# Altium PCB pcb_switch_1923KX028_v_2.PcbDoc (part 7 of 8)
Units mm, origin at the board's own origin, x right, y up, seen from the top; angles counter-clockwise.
Board outline 297.2 x 112.05 mm, 6 copper layers (Component Side, GND Layer 1, Inner Layer 1, Inner Layer 2, GND Layer 2, Solder Side), stack 1.578 mm thick; 545 components, 377 nets, 3174 pads, 1537 vias.
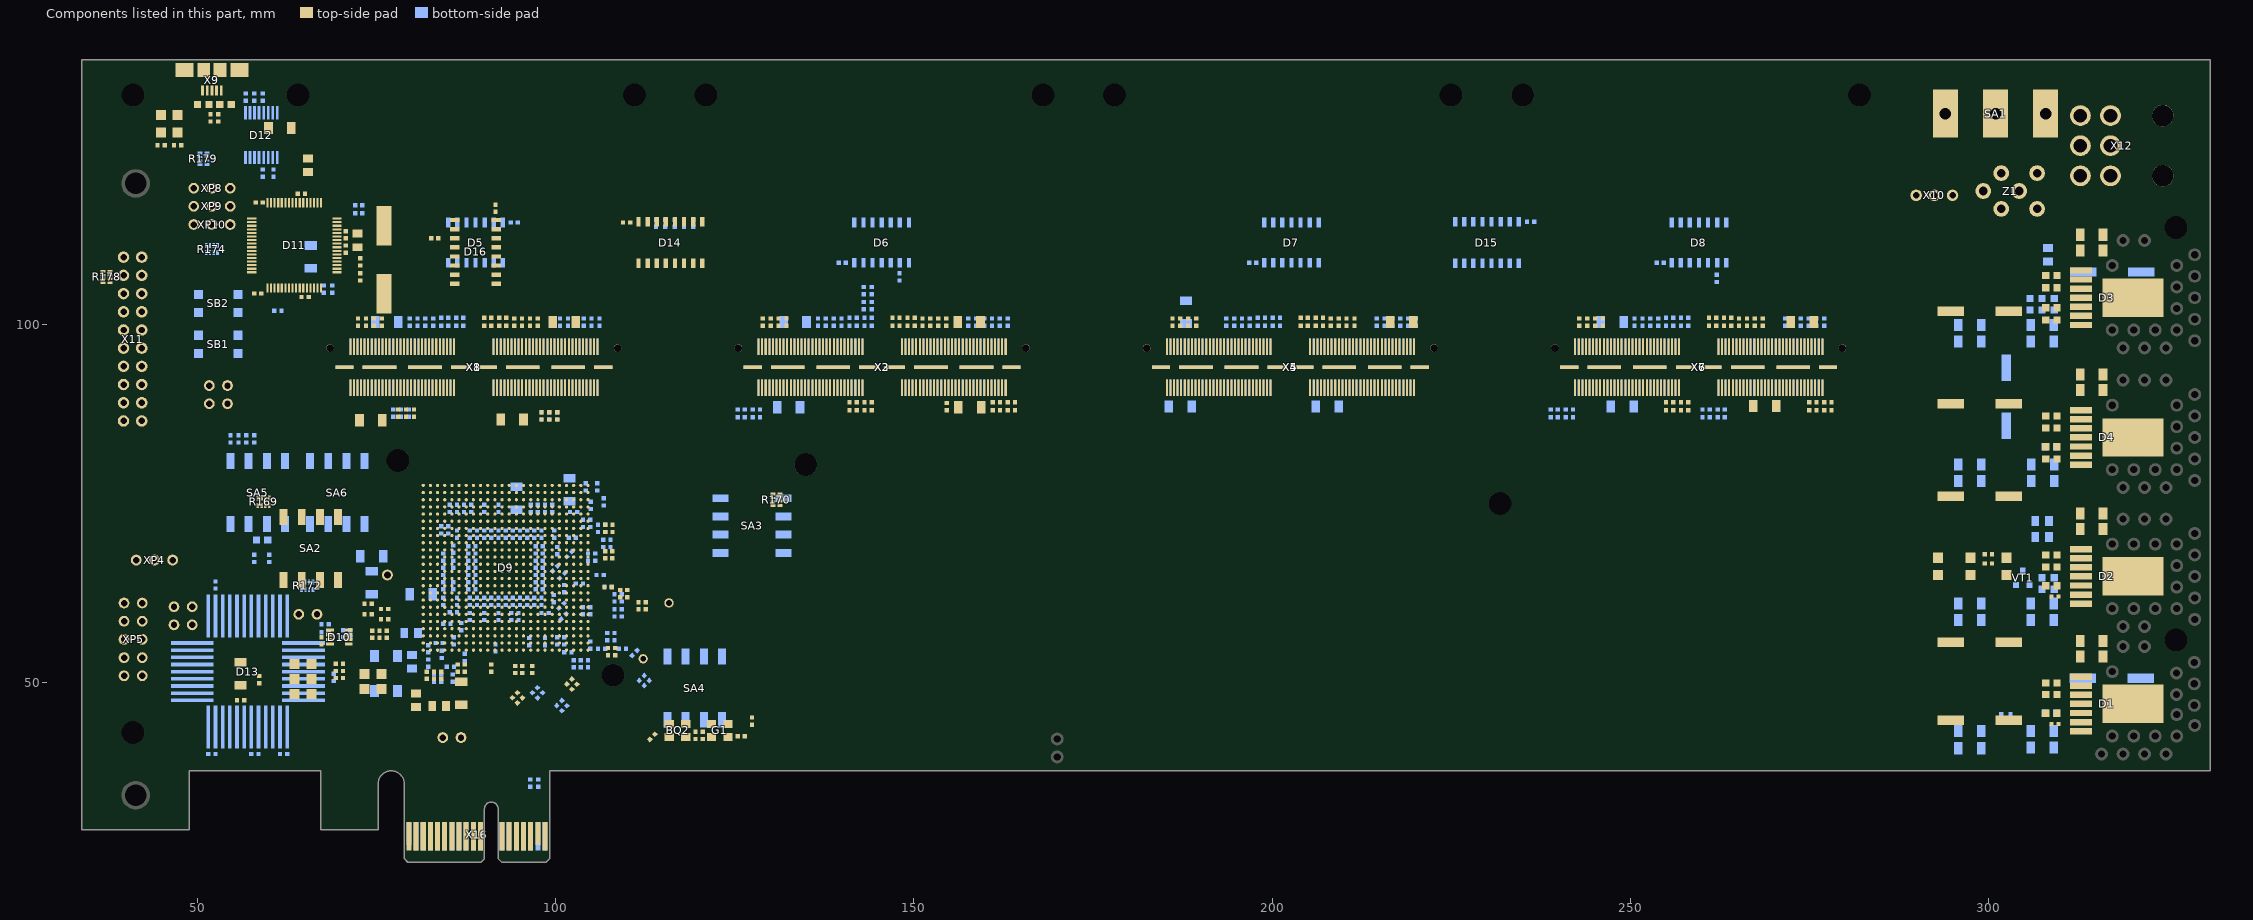
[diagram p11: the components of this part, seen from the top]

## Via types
v1: diameter 0.8, hole 0.4, Component Side to Solder Side, tented both sides, 884 vias
v2: diameter 0.5, hole 0.3, Component Side to Solder Side, tented both sides, 269 vias
v3: diameter 1, hole 0.6, Component Side to Solder Side, tented both sides, 95 vias
v4: diameter 0.5/0.5/0.3/0.3/0.5/0.5 (per signal layer), hole 0.3, Component Side to Solder Side, tented both sides, 80 vias
v5: diameter 0.5/0.3/0.3/0.5/0.3/0.5 (per signal layer), hole 0.3, Component Side to Solder Side, tented both sides, 37 vias
v6: diameter 0.5/0.3/0.3/0.3/0.3/0.5 (per signal layer), hole 0.3, Component Side to Solder Side, tented both sides, 34 vias
v7: diameter 0.5/0.5/0.5/0.3/0.5/0.5 (per signal layer), hole 0.3, Component Side to Solder Side, tented both sides, 29 vias
v8: diameter 0.5, hole 0.3, Component Side to Solder Side, 25 vias
v9: diameter 0.5/0.3/0.5/0.3/0.3/0.5 (per signal layer), hole 0.3, Component Side to Solder Side, tented both sides, 25 vias
v10: diameter 0.5/0.5/0.3/0.5/0.5/0.5 (per signal layer), hole 0.3, Component Side to Solder Side, tented both sides, 19 vias
v11: diameter 0.6, hole 0.3, Component Side to Solder Side, tented both sides, 14 vias
v12: diameter 0.8, hole 0.5, Component Side to Solder Side, tented both sides, 11 vias
v13: diameter 0.5/0.3/0.5/0.5/0.3/0.5 (per signal layer), hole 0.3, Component Side to Solder Side, tented both sides, 7 vias
v14: diameter 0.8, hole 0.4, Component Side to Solder Side, 5 vias
v15: diameter 0.5/0.5/0.5/0.5/0.5/0.5 (per signal layer), hole 0.3, Component Side to Solder Side, tented both sides, 2 vias
v16: diameter 0.8, hole 0.5, Component Side to Solder Side, 1 vias

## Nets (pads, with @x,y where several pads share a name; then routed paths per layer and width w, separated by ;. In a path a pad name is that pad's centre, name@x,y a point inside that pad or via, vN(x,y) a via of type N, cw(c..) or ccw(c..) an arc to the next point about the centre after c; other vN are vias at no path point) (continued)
pads on no net: BQ2.2 BQ2.4 D9.A4 D9.A5 D9.A6 D9.A10 D9.A11 D9.A12 D9.A13 D9.A18 D9.A19 D9.A20 D9.AA8 D9.AA9 D9.AA19 D9.AB19 D9.AC13 D9.AD13 D9.AD23 D9.B5 D9.B6 D9.B7 D9.B10 D9.B11 D9.B12 D9.B13 D9.B18 D9.B19 D9.C5 D9.C6 D9.C12 D9.C17 D9.C18 D9.C19 D9.D5 D9.D6 D9.D7 D9.D11 D9.D12 D9.D17 D9.D18 D9.D19 D9.G1 D9.H2 D9.H23 D9.J1 D9.J2 D9.J4 D9.K1 D9.K2 D9.K3 D9.K4 D9.K23 D9.K24 D9.L2 D9.L4 D9.R2 D9.R4 D9.T1 D9.T2 D9.T3 D9.T4 D9.U1 D9.U2 D9.U3 D9.U21 D9.U22 D9.V1 D9.V4 D11.9 D11.10 D11.14 D11.16 D11.29 D11.34 D11.37 D11.50 D12.15 D12.16 D13.14 D13.18 D13.19 D13.22 D13.23 D13.24 D13.25 D13.28 D15.9 R174.4 R174.8 SA1.3 SB1.2 SB1.4 SB2.2 SB2.4 X1.0 X1.2 X1.3 X1.4 X1.7 X1.9 X1.11 X1.13 X1.15 X1.16 X1.17 X1.18 X1.19 X1.20 X1.21 X1.22 X1.25 X1.26 X1.30 X1.32 X1.37 X1.63 X1.67 X1.69 X1.71 X1.73 X1.75 X1.76 X1.77 X1.78 X1.79 X1.80 X1.81 X1.82 X1.85 X1.86 X1.90 X1.92 X1.97 X2.0 X2.2 X2.3 X2.4 X2.7 X2.9 X2.11 X2.13 X2.15 X2.16 X2.17 X2.18 X2.19 X2.20 X2.21 X2.22 X2.25 X2.26 X2.29 X2.30 X2.31 X2.32 X2.35 X2.37 X2.63 X2.67 X2.69 X2.71 X2.73 X2.75 X2.76 X2.77 X2.78 X2.79 X2.80 X2.81 X2.82 X2.85 X2.86 X2.89 X2.90 X2.91 X2.92 X2.95 X2.97 X3.0 X3.3 X3.7 X3.9 X3.11 X3.13 X3.15 X3.16 X3.17 X3.18 X3.19 X3.20 X3.21 X3.22 X3.25 X3.26 X3.29 X3.30 X3.31 X3.32 X3.35 X3.37 X3.63 X3.67 X3.69 X3.71 X3.73 X3.75 X3.76 X3.77 X3.78 X3.79 X3.80 X3.81 X3.82 X3.85 X3.86 X3.89 X3.90 X3.91 X3.92 X3.95 X3.97 X4.0 X4.2 X4.3 X4.4 X4.7 X4.9 X4.11 X4.13 X4.15 X4.16 X4.17 X4.18 X4.19 X4.20 X4.21 X4.22 X4.25 X4.26 X4.29 X4.30 X4.31 X4.32 X4.35 X4.37 X4.63 X4.67 X4.69 X4.71 X4.73 X4.75 X4.76 X4.77 X4.78 X4.79 X4.80 X4.81 X4.82 X4.85 X4.86 X4.89 X4.90 X4.91 X4.92 X4.95 X4.97 X5.0 X5.3 X5.7 X5.9 X5.11 X5.13 X5.15 X5.16 X5.17 X5.18 X5.19 X5.20 X5.21 X5.22 X5.25 X5.26 X5.29 X5.30 X5.31 X5.32 X5.35 X5.37 X5.63 X5.67 X5.69 X5.71 X5.73 X5.75 X5.76 X5.77 X5.78 X5.79 X5.80 X5.81 X5.82 X5.85 X5.86 X5.89 X5.90 X5.91 X5.92 X5.95 X5.97 X6.0 X6.2 X6.3 X6.4 X6.7 X6.9 X6.11 X6.13 X6.15 X6.16 X6.17 X6.18 X6.19 X6.20 X6.21 X6.22 X6.25 X6.26 X6.29 X6.30 X6.31 X6.32 X6.35 X6.37 X6.63 X6.67 X6.69 X6.71 X6.73 X6.75 X6.76 X6.77 X6.78 X6.79 X6.80 X6.81 X6.82 X6.85 X6.86 X6.89 X6.90 X6.91 X6.92 X6.95 X6.97 X7.0 X7.3 X7.7 X7.9 X7.11 X7.13 X7.15 X7.16 X7.17 X7.18 X7.19 X7.20 X7.21 X7.22 X7.25 X7.26 X7.29 X7.30 X7.31 X7.32 X7.35 X7.37 X7.63 X7.67 X7.69 X7.71 X7.73 X7.75 X7.76 X7.77 X7.78 X7.79 X7.80 X7.81 X7.82 X7.85 X7.86 X7.89 X7.90 X7.91 X7.92 X7.95 X7.97 X8.0 X8.3 X8.7 X8.9 X8.11 X8.13 X8.15 X8.16 X8.17 X8.18 X8.19 X8.20 X8.21 X8.22 X8.25 X8.26 X8.30 X8.32 X8.37 X8.63 X8.67 X8.69 X8.71 X8.73 X8.75 X8.76 X8.77 X8.78 X8.79 X8.80 X8.81 X8.82 X8.85 X8.86 X8.90 X8.92 X8.97 X9.1 X9.4 X10.2 X12.7 X12.8 X16.A2 X16.A3 X16.A5 X16.A6 X16.A7 X16.A8 X16.A9 X16.A10 X16.B1 X16.B2 X16.B3 X16.B5 X16.B6 X16.B8 X16.B9 X16.B10 X16.B11 X16.B12

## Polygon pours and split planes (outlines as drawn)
D9_1.1V on Inner Layer 1 "TL_D9_1.1V" (solid, remove dead copper, pour order 866): 31 vertices, not listed, extent 83.4,46.7 105.705,71.7
NET_FIL_3.3V on Inner Layer 1 "IL1_NET_FIL_3.3" (solid, remove dead copper, pour order 865): 33 vertices, not listed, extent 85.8,43.3 111.9,71.4
NET_FIL_3.3V on Inner Layer 1 "IL1_NET_FIL_3.3" (solid, remove dead copper, pour order 859): 29 vertices, not listed, extent 81.7,43.3 91.4,57.9
+3.3V on Inner Layer 1 "ALL_+3.3" (solid, remove dead copper, pour order 867): 46 vertices, not listed, extent 36,38.5 307.2,127
D9_1.1V_PCIE on Inner Layer 1 "TL_D9_1.1V_PCIE" (solid, pour order 860): 84.2,52.6 85.8,52.6 86.3,53.1 86.3,57.4 86.2,57.5 85,57.5 83.8,56.3 83.8,53
+12 on Inner Layer 1 "IL2_12V" (solid, pour order 864): 316.2,119 315.2,120 315.2,132.5 314.7,133 310.2,133 309.7,132.5 309.7,126.1 306.3,126.1 306.3,135.1 307.7,136.5 316.2,136.5 318.9,133.8 318.9,119.7 318.2,119
NetSA1_2 on Inner Layer 1 "IL2_NetSA1_2" (solid, pour order 863): 18 vertices, not listed, extent 299.1,119.5 303.4,132.7
NetX12_4 on Inner Layer 1 "TL_NetXP3_4" (solid, pour order 862): 305.2,125 305.2,120.2 305.9,119.5 309.2,119.5 309.7,119 313.7,119 314.7,120 314.7,132.2 314.4,132.5 310.7,132.5 310.2,132 310.2,126 309.8,125.6 305.8,125.6
INPUTPWR on Inner Layer 1 "Inner_Layer_1_INPUTPWR" (solid, pour order 861): 301,117.8 303.2,117.8 306.2,114.8 310.3,114.8 312.9,112.2 312.9,108.7 312.2,108 305.7,108 300.2,113.5 300.2,117
GND on Inner Layer 1 "TL_DIRTY_GND" (solid, pour order 868): 316.7,136.9 316.7,120.8 309.5,120.8 305.2,116.5 305.2,114.7 305.4,114.5 310.9,114.5 313.4,112 313.4,74.5 313.4,66.4 313.4,55.5 313.4,37.7 330.9,37.7 331,37.8 331,136.9
GND on Inner Layer 1 "IL1_GND" (solid, remove dead copper, pour order 869): 34 vertices, not listed, extent 34.1,25.2 312.9,136.65
+3.3V on Component Side "TL_3.3" (solid, remove dead copper, pour order 852): 158.1,89.9 161.5,89.9 161.5,88.5 160.2,88.5 160.2,87.2 160,87 158.3,87 158.1,87.2
+3.3V on Component Side "ALL_+3.3" (solid, pour order 810): 29 vertices, not listed, extent 298.5,73.7 314.5,103.7
D9_1.1V on Component Side "TL_D9_1.1V" (solid, pour order 813): 80.4,49 81.7,49 82.5,49.8 84.2,49.8 86.1,49.8 86.4,49.5 86.4,47.9 86.1,47.6 81.8,47.6 81.5,47.9 80.4,47.9
NET_FIL_3.3V on Component Side "TL_NET_FIL_3.3V" (solid, pour order 811): 84.1,46.8 84.1,46 83.9,45.8 83.9,45 84.2,44.7 85.8,44.7 86,44.9 86,45.5 85.8,45.7 85.5,45.7 85.2,46 85.2,46.8
+3.3V on Component Side "TL_3.3V" (solid, pour order 814): 83.4,43.6 83.7,43.9 83.7,45.6 83.3,46 83.3,46.8 82.2,46.8 82.2,46 81.9,45.7 80.8,45.7 80.5,45.4 80.5,43.9 80.8,43.6
+1.1V on Component Side "TL_1.1V" (solid, pour order 815): 75.5,47.8 75.2,47.5 75.2,45.9 75.5,45.6 79.4,45.6 79.8,46 80.5,46 80.5,47.1 79.8,47.1 79.1,47.8
GND on Component Side "CS_GND_DIRECT_CONN" (solid, pour order 854): 297.7,121 297.7,114.011 297.711,114 313.2,114 313.2,121
INPUTPWR on Component Side "Inner_Layer_1_INPUTPWR" (solid, pour order 816): 17 vertices, not listed, extent 309.4,50.4 314.4,56.5
INPUTPWR on Component Side "Inner_Layer_1_INPUTPWR" (solid, pour order 818): 309.8,74.3 309.4,73.9 309.4,69.5 309.7,69.2 311.3,69.2 311.4,69.1 311.4,68.2 314.4,68.2 314.4,69 313.3,70.1 313.3,72 312,72 312,73 313.3,73 313.3,74.3
INPUTPWR on Component Side "Inner_Layer_1_INPUTPWR" (solid, pour order 819): 18 vertices, not listed, extent 309.4,87.6 314.4,93.7
+12 on Component Side "IL2_12V" (solid, pour order 807): 316.2,119 315.2,120 315.2,132.5 314.7,133 310.2,133 309.7,132.5 309.7,126.1 306.3,126.1 306.3,135.1 307.8,136.6 316.1,136.6 318.9,133.8 318.9,119.7 318.2,119
NetX12_4 on Component Side "TL_NetXP3_4" (solid, pour order 808): 313.7,119 314.7,120 314.7,132.2 314.4,132.5 310.7,132.5 310.2,132 310.2,126 309.8,125.6 308.8,125.6 305.8,125.6 305.2,125 305.2,120.2 305.9,119.5 309.2,119.5 309.7,119
NetSA1_2 on Component Side "IL2_NetSA1_2" (solid, pour order 809): 18 vertices, not listed, extent 299.1,119.5 303.4,132.7
INPUTPWR on Component Side "Inner_Layer_1_INPUTPWR" (solid, pour order 817): 19 vertices, not listed, extent 309.2,107.1 314.4,113.2
GND on Component Side "TL_DIRTY_GND" (solid, pour order 855): 26 vertices, not listed, extent 312.2,38.1 331,136.9
USB_3.3V on Component Side "TL_USB_3.3V" (solid, pour order 812): 57.1,128.1 57.4,128.4 59.1,128.4 59.3,128.2 60,128.2 60,126.6 59.3,126.6 59.1,126.4 57.4,126.4 57.1,126.7
+1.1V on Component Side "ALL_+1.1" (solid, pour order 820): 25 vertices, not listed, extent 298.5,38.1 314.5,62
+1.1V on Component Side "TL_1.1" (solid, remove dead copper, pour order 821): 79.5,102.5 79,102 79,100.2 80.8,98.4 84.6,98.4 84.6,102 84.1,102.5
+3.3V on Component Side "TL_3.3" (solid, remove dead copper, pour order 822): 80.8,93.3 81,93.5 84.6,93.5 84.8,93.3 84.8,92.7 84.6,92.5 81,92.5 80.8,92.7
+1.1V on Component Side "TL_1.1" (solid, remove dead copper, pour order 824): 100.9,95.3 101.1,95.5 104.7,95.5 104.9,95.3 104.9,94.7 104.7,94.5 101.1,94.5 100.9,94.7
+3.3V on Component Side "TL_3.3" (solid, remove dead copper, pour order 823): 101.1,93.3 101.3,93.5 104.3,93.5 104.5,93.3 104.5,92.5 101.3,92.5 101.1,92.7
+1.1V on Component Side "TL_1.1" (solid, remove dead copper, pour order 826): 92.3,95.3 92.5,95.5 96.1,95.5 96.3,95.3 96.3,94.7 96.1,94.5 92.5,94.5 92.3,94.7
+3.3V on Component Side "TL_3.3" (solid, remove dead copper, pour order 825): 92.3,93.3 92.5,93.5 96.1,93.5 96.3,93.3 96.3,92.7 96.1,92.5 92.5,92.5 92.3,92.7
+1.1V on Component Side "TL_1.1" (solid, remove dead copper, pour order 827): 101.2,98.3 104.5,98.3 104.5,99.1 104.1,99.5 103.6,99.5 103.4,99.7 103.4,100.5 102.2,100.5 102.2,99.7 102,99.5 101.6,99.5 101.2,99.1
+3.3V on Component Side "TL_3.3" (solid, remove dead copper, pour order 828): 20 vertices, not listed, extent 92.2,84.4 104.5,89.7
+1.1V on Component Side "TL_1.1" (solid, remove dead copper, pour order 829): 129.4,95.2 129.6,95.4 133.2,95.4 133.4,95.2 133.4,94.6 133.2,94.4 129.6,94.4 129.4,94.6
+1.1V on Component Side "TL_1.1" (solid, remove dead copper, pour order 830): 137.8,95.2 138,95.4 141.6,95.4 141.8,95.2 141.8,94.6 141.6,94.4 138,94.4 137.8,94.6
+1.1V on Component Side "TL_1.1" (solid, remove dead copper, pour order 831): 149.5,95.2 149.7,95.4 153.3,95.4 153.5,95.2 153.5,94.6 153.3,94.4 149.7,94.4 149.5,94.6
+1.1V on Component Side "TL_1.1" (solid, remove dead copper, pour order 832): 157.6,95.2 157.8,95.4 161.4,95.4 161.6,95.2 161.6,94.6 161.4,94.4 157.8,94.4 157.6,94.6
+3.3V on Component Side "TL_3.3" (solid, remove dead copper, pour order 833): 129.4,93.3 129.6,93.5 133.2,93.5 133.4,93.3 133.4,92.7 133.2,92.5 129.6,92.5 129.4,92.7
+3.3V on Component Side "TL_3.3" (solid, remove dead copper, pour order 835): 137.8,93.3 138,93.5 141.6,93.5 141.8,93.3 141.8,92.7 141.6,92.5 138,92.5 137.8,92.7
+3.3V on Component Side "TL_3.3" (solid, remove dead copper, pour order 834): 149.4,93.3 149.6,93.5 153.2,93.5 153.4,93.3 153.4,92.7 153.2,92.5 149.6,92.5 149.4,92.7
+3.3V on Component Side "TL_3.3" (solid, remove dead copper, pour order 836): 157.8,93.3 158,93.5 161.6,93.5 161.8,93.3 161.8,92.7 161.6,92.5 158,92.5 157.8,92.7
+3.3V on Component Side "TL_3.3" (solid, remove dead copper, pour order 837): 186.3,93.3 186.5,93.5 190.1,93.5 190.3,93.3 190.3,92.7 190.1,92.5 186.5,92.5 186.3,92.7
+3.3V on Component Side "TL_3.3" (solid, remove dead copper, pour order 838): 194.7,93.3 194.9,93.5 198.5,93.5 198.7,93.3 198.7,92.7 198.5,92.5 194.9,92.5 194.7,92.7
+3.3V on Component Side "TL_3.3" (solid, remove dead copper, pour order 839): 207.2,93.4 207.3,93.5 210.9,93.5 211.1,93.3 211.1,92.7 210.9,92.5 207.3,92.5 207.2,92.6
+3.3V on Component Side "TL_3.3" (solid, remove dead copper, pour order 840): 214.1,93.3 214.3,93.5 217.9,93.5 218.1,93.3 218.1,92.7 217.9,92.5 214.3,92.5 214.1,92.7
+1.1V on Component Side "TL_1.1" (solid, remove dead copper, pour order 841): 70.8,102.2 71,102.4 74.6,102.4 74.8,102.2 74.8,101.6 74.6,101.4 71,101.4 70.8,101.6
+3.3V on Component Side "TL_3.3" (solid, remove dead copper, pour order 842): 72.3,93.3 72.5,93.5 76.1,93.5 76.3,93.3 76.3,92.7 76.1,92.5 72.5,92.5 72.3,92.7
+3.3V on Component Side "TL_3.3" (solid, remove dead copper, pour order 843): 20 vertices, not listed, extent 72.2,84.2 84.8,89.7
+1.1V on Component Side "TL_1.1" (solid, remove dead copper, pour order 844): 158.1,98.3 161,98.3 161,99.1 160.6,99.5 160.1,99.5 159.9,99.7 159.9,100.5 158.7,100.5 158.7,99.7 158.5,99.5 158.3,99.5 158.1,99.3
+1.1V on Component Side "TL_1.1" (solid, remove dead copper, pour order 845): 198.5,98.2 195,98.2 193.9,99.3 190,99.3 189,100.3 189,102.4 189.2,102.6 196.5,102.6 198.5,100.6
+3.3V on Component Side "TL_3.3" (solid, remove dead copper, pour order 846): 213.7,88.6 213.7,87.7 214.1,87.3 216.5,87.3 218.3,89.1 218.5,89.3 218.5,89.7 214.8,89.7
+1.1V on Component Side "TL_1.1" (solid, remove dead copper, pour order 847): 218.5,98.3 214.8,98.3 213.8,99.3 211.2,99.3 210.6,99.9 210.6,102.3 210.9,102.6 216.5,102.6 218.5,100.6
+1.1V on Component Side "TL_1.1" (solid, remove dead copper, pour order 848): 255.5,98.3 251.8,98.3 250.8,99.3 246.7,99.3 246,100 246,102.3 246.3,102.6 252.5,102.6 255.5,99.6
+1.1V on Component Side "TL_1.1" (solid, remove dead copper, pour order 849): 275.5,98.3 271.8,98.3 270.8,99.3 270.4,99.7 268.8,101.3 268.8,102.1 269.1,102.4 274.4,102.4 274.8,102 274.8,99.2 275.5,99.2
+3.3V on Component Side "TL_3.3" (solid, remove dead copper, pour order 850): 255.5,89.7 255.5,88.6 254.4,87.5 251.7,87.5 251.4,87.8 251.4,87.9 251.4,89.4 251.7,89.7
+3.3V on Component Side "TL_3.3" (solid, remove dead copper, pour order 851): 275.5,89.7 275.5,88.6 274.7,87.8 274.7,87.2 274.2,86.7 270.3,86.7 270.1,86.9 270.1,89.5 270.3,89.7
GND on Component Side "TL_GND_X" (solid, pour order 853): 67.1,95 67.1,93.1 282.7,93 282.7,95
GND on Component Side "TL_GND" (solid, remove dead copper, pour order 856): 314.3,38 314.3,136.5 34.3,136.5 34.3,78 105.5,78 105.5,38.1
GND on Component Side "TL_GND" (solid, remove dead copper, pour order 857): 27 vertices, not listed, extent 34.2,29.8 108.197,80
GND on Component Side "TL_GND_1923" (solid, remove dead copper, pour order 858): 78.5,80 108,80 108,51 78.5,51
+3.3V on Solder Side "TL_3.3" (solid, remove dead copper, pour order 935): 77.9,64.5 77.6,64.2 77.6,63.7 77.8,63.5 81.3,63.5 81.6,63.2 81.6,61.5 83.3,61.5 83.3,63.7 82.5,64.5 80.8,64.5
+1.1V on Solder Side "TL_1.1V" (solid, remove dead copper, pour order 931): 77.6,63 77.3,63.3 75.6,63.3 75.2,62.9 74.3,62.9 74.3,61.7 75.2,61.7 75.7,61.2 77.3,61.2 77.6,61.5
+3.3V on Solder Side "BL_3.3" (solid, remove dead copper, pour order 939): 80.8,45.7 80.6,45.5 80.6,43.9 80.8,43.7 83.3,43.7 83.5,43.9 83.5,45.5 83.3,45.7
D9_1.1V on Solder Side "BL_D9_1.1" (solid, remove dead copper, pour order 937): 83.7,49.7 83.5,49.5 83.5,47.9 83.7,47.7 86.2,47.7 86.4,47.9 86.4,49.5 86.2,49.7
+1.1V on Solder Side "BL_1.1" (solid, remove dead copper, pour order 933): 17 vertices, not listed, extent 75.3,45.7 79.3,48
+1.1V on Solder Side "TL_1.1" (solid, remove dead copper, pour order 929): 273.5,101.2 273.8,101.5 273.8,102.3 273.3,102.8 267.3,102.8 263.6,99.1 263.6,98.1 267,98.1 267,99 269.2,101.2
+3.3V on Solder Side "TL_3.3" (solid, remove dead copper, pour order 927): 271.5,89.6 271.3,89.4 271.3,87.7 271.5,87.5 274.3,87.5 274.5,87.7 274.5,89.4 274.3,89.6
+3.3V on Solder Side "TL_3.3" (solid, remove dead copper, pour order 925): 263.6,89.9 267,89.9 267,87.8 266.7,87.5 263.6,87.5
+3.3V on Solder Side "TL_3.3" (solid, remove dead copper, pour order 923): 251.6,89.6 251.4,89.4 251.4,87.8 251.6,87.6 254.2,87.6 254.4,87.8 254.4,89.4 254.2,89.6
+3.3V on Solder Side "TL_3.3" (solid, remove dead copper, pour order 921): 243.6,89.9 243.6,88.8 245.9,86.5 247.7,86.5 247.9,86.7 247.9,89.4 247.9,89.5 247.5,89.9
+1.1V on Solder Side "BL_1.1" (solid, remove dead copper, pour order 920): 243.6,98.2 247,98.2 247.2,98.4 247.2,100.4 247.9,101.1 248.8,101.1 249,101.3 249,102.2 248.8,102.4 245.8,102.4 245.5,102.1 245.5,101.5 243.6,99.6
+1.1V on Solder Side "BL_1.1_X5" (solid, remove dead copper, pour order 919): 206.6,98.2 210,98.2 212.6,100.8 214.6,100.8 215.6,101.8 215.6,102.5 215.4,102.7 210.7,102.7 209.3,101.3 207.9,101.3 206.6,100
+3.3V on Solder Side "TL_3.3" (solid, remove dead copper, pour order 918): 207.6,89.5 207.9,89.8 210.6,89.8 210.6,89.3 211.4,88.5 212.2,88.5 212.5,88.2 212.5,86.7 212.3,86.5 208,86.5 208,88.8 207.6,89.2
+3.3V on Solder Side "TL_3.3" (solid, remove dead copper, pour order 917): 214.2,93.2 214.5,93.5 217.8,93.5 218,93.3 218,92.7 217.8,92.5 214.5,92.5 214.2,92.8
+3.3V on Solder Side "TL_3.3" (solid, remove dead copper, pour order 916): 206.6,93.1 207,93.5 210.8,93.5 211,93.3 211,92.7 210.7,92.4 206.6,92.4
+3.3V on Solder Side "TL_3.3" (solid, remove dead copper, pour order 915): 194.8,93.2 195.1,93.5 198.3,93.5 198.6,93.2 198.6,92.8 198.3,92.5 195.1,92.5 194.8,92.8
+3.3V on Solder Side "TL_3.3" (solid, remove dead copper, pour order 914): 186.6,89.6 186.6,89.8 189.9,89.8 190.1,89.6 190.1,87.5 189.7,87.1 187.9,87.1 187.5,87.5 187.5,88.7
+3.3V on Solder Side "TL_3.3" (solid, remove dead copper, pour order 913): 186.4,93.2 186.7,93.5 190,93.5 190.2,93.3 190.2,92.6 190,92.4 186.7,92.4 186.4,92.7
+1.1V on Solder Side "BL_1.1_X5" (solid, remove dead copper, pour order 912): 186.6,98.2 190,98.2 190,100.8 190.5,101.3 194.1,101.3 194.4,101.6 194.4,102.5 194.2,102.7 189.1,102.7 186.6,100.2
+3.3V on Solder Side "TL_3.3" (solid, remove dead copper, pour order 911): 157.9,93.2 158.2,93.5 161.5,93.5 161.7,93.3 161.7,92.7 161.5,92.5 158.2,92.5 157.9,92.8
+1.1V on Solder Side "TL_1.1" (solid, remove dead copper, pour order 910): 157.7,95.1 158,95.4 161.3,95.4 161.5,95.2 161.5,94.6 161.3,94.4 158,94.4 157.7,94.7
+1.1V on Solder Side "BL_1.1" (solid, remove dead copper, pour order 909): 149.6,95.1 149.9,95.4 153.2,95.4 153.4,95.2 153.4,94.6 153.2,94.4 149.9,94.4 149.6,94.7
+3.3V on Solder Side "TL_3.3" (solid, remove dead copper, pour order 908): 149.5,93.2 149.8,93.5 153.1,93.5 153.3,93.3 153.3,92.7 153.1,92.5 149.8,92.5 149.5,92.8
+1.1V on Solder Side "TL_1.1" (solid, remove dead copper, pour order 907): 137.9,95.1 138.2,95.4 141.5,95.4 141.8,95.1 141.8,94.7 141.6,94.5 138.1,94.5 137.9,94.7
+3.3V on Solder Side "TL_3.3" (solid, remove dead copper, pour order 906): 137.8,93.2 138.1,93.5 141.5,93.5 141.8,93.2 141.8,92.8 141.6,92.6 138,92.6 137.8,92.8
+1.1V on Solder Side "BL_1.1_X3" (solid, remove dead copper, pour order 905): 129.65,98.2 129.65,98.85 130.4,99.6 132.6,99.6 133,99.2 133,98.2
+1.1V on Solder Side "TL_1.1" (solid, remove dead copper, pour order 904): 129.5,95.25 129.65,95.4 129.65,95.55 133.05,95.55 133.4,95.2 133.4,94.6 133.3,94.5 129.7,94.5 129.5,94.7
+3.3V on Solder Side "TL_3.3" (solid, remove dead copper, pour order 903): 141.5,86.5 141.5,87.2 140.2,88.5 138.5,88.5 137.2,87.2 133.2,87.2 133,87.4 130.3,87.4 130.3,86.8 131.4,85.7 140.7,85.7
+3.3V on Solder Side "BL_3.3_X3" (solid, remove dead copper, pour order 902): 130.1,89.5 130.1,89.7 133,89.7 133,87.3 131.7,87.3 131.7,88.8 130.3,88.8 130.3,89.3
+3.3V on Solder Side "TL_3.3" (solid, remove dead copper, pour order 901): 129.5,93.2 129.8,93.5 133.2,93.5 133.4,93.3 133.4,92.7 133.3,92.6 129.7,92.6 129.5,92.8
+3.3V on Solder Side "TL_3.3" (solid, remove dead copper, pour order 899): 101.2,93.2 101.4,93.4 104.1,93.4 104.3,93.2 104.3,92.8 104.1,92.6 101.4,92.6 101.2,92.8
INPUTPWR on Solder Side "Inner_Layer_1_INPUTPWR" (solid, pour order 887): 309.6,56.6 309.3,56.3 309.3,50.5 309.9,49.9 315.1,49.9 315.1,51.275 312.6,51.275 312,51.875 312,56.3 311.7,56.6
+12 on Solder Side "IL2_12V" (solid, pour order 882): 316.2,119 315.2,120 315.2,132.5 314.7,133 310.2,133 309.7,132.5 309.7,126.1 306.3,126.1 306.3,135.1 307.7,136.5 316.2,136.5 318.9,133.8 318.9,119.7 318.2,119
NetX12_4 on Solder Side "TL_NetXP3_4" (solid, pour order 880): 305.2,125 305.2,120.2 305.9,119.5 309.2,119.5 309.7,119 313.7,119 314.7,120 314.7,132.2 314.4,132.5 310.7,132.5 310.2,132 310.2,126 309.8,125.6 305.8,125.6
NetSA1_2 on Solder Side "IL2_NetSA1_2" (solid, pour order 881): 300.7,119.5 302.9,119.5 303.4,120 303.4,125.4 302.7,126.1 302.7,132.7 299.3,132.7 299.3,126.1 299.1,125.9 299.1,123.1 300.2,122 300.2,120
GND on Solder Side "TL_DIRTY_GND" (solid, remove dead copper, pour order 891): 316.7,136.6 316.7,120.3 298.6,120.3 297.7,119.4 297.7,116.5 301,113.2 311.6,113.2 311.7,113.2 312.3,112.6 312.3,38 330.6,38 330.6,136.6
INPUTPWR on Solder Side "Inner_Layer_1_INPUTPWR" (solid, pour order 888): 309.7,113.3 309.4,113 309.4,107.2 310,106.6 315.2,106.6 315.2,107.975 312.7,107.975 312.1,108.575 312.1,113 311.8,113.3
+3.3V on Solder Side "ALL_+3.3" (solid, pour order 883): 23 vertices, not listed, extent 298.5,91.5 306.4,100.6
+3.3V on Solder Side "ALL_+3.3" (solid, pour order 884): 18 vertices, not listed, extent 298.5,77.1 306.4,81.1
+1.1V on Solder Side "ALL_+1.1" (solid, pour order 885): 18 vertices, not listed, extent 298.5,57.7 306.4,61.7
+1.1V on Solder Side "ALL_+1.1" (solid, pour order 886): 18 vertices, not listed, extent 298.5,39.9 306.4,43.9
INPUTPWR on Solder Side "Inner_Layer_1_INPUTPWR" (solid, pour order 889): 309.7,74.4 309.4,74.1 309.4,69.4 309.7,69.1 311.8,69.1 312.1,69.4 312.1,74.1 311.8,74.4
INPUTPWR on Solder Side "Inner_Layer_1_INPUTPWR" (solid, pour order 890): 309.7,93.8 309.4,93.5 309.4,88.8 309.7,88.5 311.8,88.5 312.1,88.8 312.1,93.5 311.8,93.8
GND on Solder Side "TL_GND_X" (solid, pour order 941): 67.1,95.8 67.1,92.2 282.7,92.2 282.7,95.8
+1.1V on Solder Side "BL_1.1" (solid, remove dead copper, pour order 892): 71,102.4 70.8,102.2 70.8,101.6 71,101.4 71.5,101.4 72.6,100.3 72.6,98.3 76,98.3 76,101.4 75,102.4
+3.3V on Solder Side "TL_3.3" (solid, remove dead copper, pour order 893): 72.5,93.3 72.7,93.5 76.1,93.5 76.3,93.3 76.3,92.7 76.1,92.5 72.7,92.5 72.5,92.7
+3.3V on Solder Side "TL_3.3" (solid, remove dead copper, pour order 894): 72.5,89.3 72.7,89.5 76.1,89.5 76.3,89.3 76.3,88.7 76.1,88.5 72.7,88.5 72.5,88.7
+3.3V on Solder Side "TL_3.3" (solid, remove dead copper, pour order 895): 80.8,93.3 81,93.5 84.6,93.5 84.8,93.3 84.8,92.7 84.6,92.5 81,92.5 80.8,92.7
+3.3V on Solder Side "TL_3.3" (solid, remove dead copper, pour order 896): 80.8,89.5 81,89.7 84.6,89.7 84.8,89.5 84.8,88.9 84.6,88.7 81,88.7 80.8,88.9
+1.1V on Solder Side "TL_3.3" (solid, remove dead copper, pour order 897): 92.5,95.3 92.7,95.5 96.1,95.5 96.3,95.3 96.3,94.7 96.1,94.5 92.7,94.5 92.5,94.7
+3.3V on Solder Side "TL_3.3" (solid, remove dead copper, pour order 898): 92.5,93.3 92.7,93.5 96.1,93.5 96.3,93.3 96.3,92.7 96.1,92.5 92.7,92.5 92.5,92.7
+3.3V on Solder Side "TL_3.3" (solid, remove dead copper, pour order 900): 92.4,89.2 92.7,89.5 96.1,89.5 96.3,89.3 96.3,88.7 96.2,88.6 92.6,88.6 92.4,88.8
GND on Solder Side "BL_GND" (solid, remove dead copper, pour order 943): 23 vertices, not listed, extent 34.2,29.8 311.8,136.5
+3.3V on Inner Layer 2 "IL2_3.3" (solid, remove dead copper, pour order 870): 25 vertices, not listed, extent 105.1,51.5 124.9,56.5
+1.1V on Inner Layer 2 "ALL_+1.1" (solid, remove dead copper, pour order 878): 31 vertices, not listed, extent 61.7,38.5 305.1,106.2
NetX12_4 on Inner Layer 2 "TL_NetXP3_4" (solid, pour order 875): 305.2,125 305.2,120.2 305.9,119.5 309.2,119.5 309.7,119 313.7,119 314.7,120 314.7,132.2 314.4,132.5 310.7,132.5 310.2,132 310.2,126 309.8,125.6 305.8,125.6
+12 on Inner Layer 2 "IL2_12V" (solid, pour order 873): 316.2,119 315.2,120 315.2,132.5 314.7,133 310.2,133 309.7,132.5 309.7,126.1 306.3,126.1 306.3,135.1 307.7,136.5 316.2,136.5 318.9,133.8 318.9,119.7 318.2,119
NetSA1_2 on Inner Layer 2 "IL2_NetSA1_2" (solid, pour order 874): 300.7,119.5 302.9,119.5 303.4,120 303.4,125.4 302.8,126 302.7,126.1 302.7,132.7 299.3,132.7 299.3,126.1 299.1,125.9 299.1,123.1 300.2,122 300.2,120
GND on Inner Layer 2 "TL_DIRTY_GND" (solid, pour order 876): 316.7,136.9 316.7,120.8 303.5,120.8 303.5,116.4 305.2,114.7 305.4,114.5 310.9,114.5 313.4,112 313.4,37.7 330.9,37.7 331,37.8 331,136.9
GND on Inner Layer 2 "CS_GND_DIRECT_CONN" (solid, pour order 877): 297.7,120.5 297.7,117 306.2,117 306.2,120.5
USB_3.3V on Inner Layer 2 "IL2_USB_3.3V" (solid, pour order 871): 57.1,128.4 57.1,126.6 59.3,124.4 62.1,124.4 62.1,123 62.4,122.7 64.1,122.7 64.3,122.7 64.6,123 64.6,125 61.2,128.4
GND on Inner Layer 2 "IL1_GND" (solid, remove dead copper, pour order 879): 34 vertices, not listed, extent 34.1,25.2 312.9,136.65
INPUTPWR on Inner Layer 2 "Inner_Layer_1_INPUTPWR" (solid, pour order 872): 300.2,116.4 301.2,117.4 303.2,117.4 306.8,113.8 311.4,113.8 313.2,112 313.2,51.4 313,51.2 309,51.2 306.7,53.5 306.7,107 300.2,113.5
GND on GND Layer 1 "TL_DIRTY_GND" (solid, remove dead copper, pour order 953): 313.4,38 330.6,38 330.6,136.6 306.8,136.6 306.8,114.1 311.4,114.1 313.4,112.1
+12 on GND Layer 1 "IL2_12V" (solid, pour order 947): 316.2,119 315.2,120 315.2,132.5 314.7,133 310.2,133 309.7,132.5 309.7,126.1 306.3,126.1 306.3,135.1 307.7,136.5 316.2,136.5 318.9,133.8 318.9,119.7 318.2,119
NetX12_4 on GND Layer 1 "TL_NetXP3_4" (solid, pour order 945): 305.2,125 305.2,120.2 305.9,119.5 309.2,119.5 309.7,119 313.7,119 314.7,120 314.7,132.2 314.4,132.5 310.7,132.5 310.2,132 310.2,126 309.8,125.6 305.8,125.6
INPUTPWR on GND Layer 1 "Inner_Layer_1_INPUTPWR" (solid, pour order 949): 300.2,116.2 301.3,117.3 302.2,117.3 305.6,113.9 311.3,113.9 313.2,112 313.2,38 307.7,38 307.7,52.5 307.3,52.9 307.3,106.4 300.2,113.5
GND on GND Layer 1 "INT_LAYER_GND" (solid, remove dead copper, pour order 951): 29 vertices, not listed, extent 34.2,25.3 307.5,136.6
GND on GND Layer 2 "INT_LAYER_GND" (solid, remove dead copper, pour order 961): 29 vertices, not listed, extent 34.2,25.3 307.5,136.6
+12 on GND Layer 2 "IL2_12V" (solid, pour order 959): 316.2,119 315.2,120 315.2,132.5 314.7,133 310.2,133 309.7,132.5 309.7,126.1 306.3,126.1 306.3,135.1 307.7,136.5 316.2,136.5 318.9,133.8 318.9,119.7 318.2,119
NetX12_4 on GND Layer 2 "TL_NetXP3_4" (solid, pour order 957): 305.2,125 305.2,120.2 305.9,119.5 309.2,119.5 309.7,119 313.7,119 314.7,120 314.7,132.2 314.4,132.5 310.7,132.5 310.2,132 310.2,126 309.8,125.6 305.8,125.6
GND on GND Layer 2 "TL_DIRTY_GND" (solid, remove dead copper, pour order 963): 313.4,38 330.6,38 330.6,136.6 306.8,136.6 306.8,113.9 311.6,113.9 313.4,112.1
INPUTPWR on GND Layer 2 "Inner_Layer_1_INPUTPWR" (solid, pour order 955): 300.2,116.2 301.3,117.3 302.2,117.3 305.8,113.7 311.5,113.7 313.2,112 313.2,38 307.7,38 307.7,52.5 307.3,52.9 307.3,106.4 300.2,113.5

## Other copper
Component Side:
  region net GND: 315.4,48 315.4,46 319.2,46 319.2,43.9 321.2,43.9 321.2,46 324.9,46 324.9,48 321.2,48 321.2,50.1 319.2,50.1 319.2,48
  region net GND: 315.4,65.8 315.4,63.8 319.2,63.8 319.2,61.7 321.2,61.7 321.2,63.8 324.9,63.8 324.9,65.8 321.2,65.8 321.2,67.9 319.2,67.9 319.2,65.8
  region net GND: 315.4,85.2 315.4,83.2 319.2,83.2 319.2,81.1 321.2,81.1 321.2,83.2 324.9,83.2 324.9,85.2 321.2,85.2 321.2,87.3 319.2,87.3 319.2,85.2
  pour cut-out: 316.8,109.2 316.8,113.6 315.2,113.6 315.2,109.2
  pour cut-out: 316.8,89.7 316.8,94.1 315.2,94.1 315.2,89.7
  pour cut-out: 316.8,70.3 316.8,74.7 315.2,74.7 315.2,70.3
  pour cut-out: 316.8,52.5 316.8,56.9 315.2,56.9 315.2,52.5
  pour cut-out: 315.7,81.3 315.7,87.1 324.7,87.1 324.7,81.3
  pour cut-out: 315.7,100.8 315.7,106.6 324.7,106.6 324.7,100.8
  pour cut-out: 315.7,61.9 315.7,67.7 324.7,67.7 324.7,61.9
  pour cut-out: 315.7,44.1 315.7,49.9 324.7,49.9 324.7,44.1
  region net GND: 315.4,104.7 315.4,102.7 319.2,102.7 319.2,100.6 321.2,100.6 321.2,102.7 324.9,102.7 324.9,104.7 321.2,104.7 321.2,106.8 319.2,106.8 319.2,104.7
  pour cut-out: 58.6,74.175 59.8,74.175 59.8,76.025 58.6,76.025
  pour cut-out: 131.8,75 131.8,76 130.9,76 130.9,75
  pour cut-out: 300.8,102.65 304.9,102.65 304.9,102.35 300.8,102.35
  pour cut-out: 300.8,101.25 304.9,101.25 304.9,100.95 300.8,100.95
  pour cut-out: 300.8,89.75 304.9,89.75 304.9,89.45 300.8,89.45
  pour cut-out: 300.8,88.35 304.9,88.35 304.9,88.05 300.8,88.05
  pour cut-out: 300.8,76.85 304.9,76.85 304.9,76.55 300.8,76.55
  pour cut-out: 300.8,75.45 304.9,75.45 304.9,75.15 300.8,75.15
  pour cut-out: 300.8,56.45 304.9,56.45 304.9,56.15 300.8,56.15
  pour cut-out: 300.8,55.05 304.9,55.05 304.9,54.75 300.8,54.75
  pour cut-out: 300.8,45.55 304.9,45.55 304.9,45.25 300.8,45.25
  pour cut-out: 300.8,44.15 304.9,44.15 304.9,43.85 300.8,43.85
  pour cut-out: 292.7,45.55 296.8,45.55 296.8,45.25 292.7,45.25
  pour cut-out: 292.7,44.15 296.8,44.15 296.8,43.85 292.7,43.85
  pour cut-out: 292.7,56.45 296.8,56.45 296.8,56.15 292.7,56.15
  pour cut-out: 292.7,55.05 296.8,55.05 296.8,54.75 292.7,54.75
  pour cut-out: 292.7,76.85 296.8,76.85 296.8,76.55 292.7,76.55
  pour cut-out: 292.7,75.45 296.8,75.45 296.8,75.15 292.7,75.15
  pour cut-out: 292.7,89.75 296.8,89.75 296.8,89.45 292.7,89.45
  pour cut-out: 292.7,88.35 296.8,88.35 296.8,88.05 292.7,88.05
  pour cut-out: 292.7,102.65 296.8,102.65 296.8,102.35 292.7,102.35
  pour cut-out: 292.7,101.25 296.8,101.25 296.8,100.95 292.7,100.95
  pour cut-out: 216.1,101.35 215.7,101.35 215.7,99.25 216.1,99.25
  pour cut-out: 217.3,101.35 216.9,101.35 216.9,99.25 217.3,99.25
  pour cut-out: 273.2,101.35 272.8,101.35 272.8,99.25 273.2,99.25
  pour cut-out: 272,101.35 271.6,101.35 271.6,99.25 272,99.25
  pour cut-out: 100.5,54.1 100.5,53.1 100.2,53.1 100.2,54.1
  pour cut-out: 99.5,54.1 99.5,52 99.2,52 99.2,54.1
  pour cut-out: 98.5,54.1 98.5,50.6 98.2,50.6 98.2,54.1
  pour cut-out: 41,41 cw(c41,43) 39,43 cw(c41,43) 41,45 cw(c41,43) 43,43 cw(c41,43)
  pour cut-out: 326.2,53.9 ccw(c326.2,55.9) 328.2,55.9 ccw(c326.2,55.9) 326.2,57.9 ccw(c326.2,55.9) 324.2,55.9 ccw(c326.2,55.9)
  pour cut-out: 326.2,111.5 ccw(c326.2,113.5) 328.2,113.5 ccw(c326.2,113.5) 326.2,115.5 ccw(c326.2,113.5) 324.2,113.5 ccw(c326.2,113.5)
  pour cut-out: 324.35,118.725 ccw(c324.35,120.725) 326.35,120.725 ccw(c324.35,120.725) 324.35,122.725 ccw(c324.35,120.725) 322.35,120.725 ccw(c324.35,120.725)
  pour cut-out: 324.35,127.125 ccw(c324.35,129.125) 326.35,129.125 ccw(c324.35,129.125) 324.35,131.125 ccw(c324.35,129.125) 322.35,129.125 ccw(c324.35,129.125)
  pour cut-out: 79,50.5 cw(c79,52) 77.5,52 cw(c79,52) 79,53.5 cw(c79,52) 80.5,52 cw(c79,52)
  region: 79,51.5 cw(c79,52) 78.5,52 cw(c79,52) 79,52.5 cw(c79,52) 79.5,52 cw(c79,52)
  region: 36,134 cw(c36,134.5) 35.5,134.5 cw(c36,134.5) 36,135 cw(c36,134.5) 36.5,134.5 cw(c36,134.5)
  pour cut-out: 36,133 cw(c36,134.5) 34.5,134.5 cw(c36,134.5) 36,136 cw(c36,134.5) 37.5,134.5 cw(c36,134.5)
  pour cut-out: 328.2,38.5 cw(c328.2,40) 326.7,40 cw(c328.2,40) 328.2,41.5 cw(c328.2,40) 329.7,40 cw(c328.2,40)
  region: 328.2,39.5 cw(c328.2,40) 327.7,40 cw(c328.2,40) 328.2,40.5 cw(c328.2,40) 328.7,40 cw(c328.2,40)
  pour cut-out: 328.2,132.5 cw(c328.2,134) 326.7,134 cw(c328.2,134) 328.2,135.5 cw(c328.2,134) 329.7,134 cw(c328.2,134)
  region: 328.2,133.5 cw(c328.2,134) 327.7,134 cw(c328.2,134) 328.2,134.5 cw(c328.2,134) 328.7,134 cw(c328.2,134)
  pour cut-out: 64,130 cw(c64,132) 62,132 cw(c64,132) 64,134 cw(c64,132) 66,132 cw(c64,132)
  pour cut-out: 111,130 cw(c111,132) 109,132 cw(c111,132) 111,134 cw(c111,132) 113,132 cw(c111,132)
  pour cut-out: 121,130 cw(c121,132) 119,132 cw(c121,132) 121,134 cw(c121,132) 123,132 cw(c121,132)
  pour cut-out: 168,130 cw(c168,132) 166,132 cw(c168,132) 168,134 cw(c168,132) 170,132 cw(c168,132)
  pour cut-out: 178,130 cw(c178,132) 176,132 cw(c178,132) 178,134 cw(c178,132) 180,132 cw(c178,132)
  pour cut-out: 225,130 cw(c225,132) 223,132 cw(c225,132) 225,134 cw(c225,132) 227,132 cw(c225,132)
  pour cut-out: 235,130 cw(c235,132) 233,132 cw(c235,132) 235,134 cw(c235,132) 237,132 cw(c235,132)
  pour cut-out: 282,130 cw(c282,132) 280,132 cw(c282,132) 282,134 cw(c282,132) 284,132 cw(c282,132)
  pour cut-out: 108,49 cw(c108,51) 106,51 cw(c108,51) 108,53 cw(c108,51) 110,51 cw(c108,51)
  pour cut-out: 78,79 cw(c78,81) 76,81 cw(c78,81) 78,83 cw(c78,81) 80,81 cw(c78,81)
  pour cut-out: 41,130 cw(c41,132) 39,132 cw(c41,132) 41,134 cw(c41,132) 43,132 cw(c41,132)
  pour cut-out: 134.9,78.4 cw(c134.9,80.4) 132.9,80.4 cw(c134.9,80.4) 134.9,82.4 cw(c134.9,80.4) 136.9,80.4 cw(c134.9,80.4)
  pour cut-out: 231.8,73 cw(c231.8,75) 229.8,75 cw(c231.8,75) 231.8,77 cw(c231.8,75) 233.8,75 cw(c231.8,75)
Inner Layer 1:
  pour cut-out: 89.546,30.625 89.546,26.375 89.862,26.375 89.862,30.625
  pour cut-out: 79.354,30.625 79.354,26.375 79.025,26.375 79.025,30.625
  pour cut-out: 92.454,30.625 92.454,26.375 92.025,26.375 92.025,30.625
  pour cut-out: 98.646,30.625 98.646,26.375 98.975,26.375 98.975,30.625
  pour cut-out: 121,130 cw(c121,132) 119,132 cw(c121,132) 121,134 cw(c121,132) 123,132 cw(c121,132)
  pour cut-out: 168,130 cw(c168,132) 166,132 cw(c168,132) 168,134 cw(c168,132) 170,132 cw(c168,132)
  pour cut-out: 178,130 cw(c178,132) 176,132 cw(c178,132) 178,134 cw(c178,132) 180,132 cw(c178,132)
  pour cut-out: 225,130 cw(c225,132) 223,132 cw(c225,132) 225,134 cw(c225,132) 227,132 cw(c225,132)
  pour cut-out: 235,130 cw(c235,132) 233,132 cw(c235,132) 235,134 cw(c235,132) 237,132 cw(c235,132)
  pour cut-out: 282,130 cw(c282,132) 280,132 cw(c282,132) 282,134 cw(c282,132) 284,132 cw(c282,132)
  pour cut-out: 41,41 cw(c41,43) 39,43 cw(c41,43) 41,45 cw(c41,43) 43,43 cw(c41,43)
  pour cut-out: 78,79 cw(c78,81) 76,81 cw(c78,81) 78,83 cw(c78,81) 80,81 cw(c78,81)
  pour cut-out: 108,49 cw(c108,51) 106,51 cw(c108,51) 108,53 cw(c108,51) 110,51 cw(c108,51)
  pour cut-out: 326.2,53.9 cw(c326.2,55.9) 324.2,55.9 cw(c326.2,55.9) 326.2,57.9 cw(c326.2,55.9) 328.2,55.9 cw(c326.2,55.9)
  pour cut-out: 326.2,111.5 cw(c326.2,113.5) 324.2,113.5 cw(c326.2,113.5) 326.2,115.5 cw(c326.2,113.5) 328.2,113.5 cw(c326.2,113.5)
  pour cut-out: 324.35,118.725 cw(c324.35,120.725) 322.35,120.725 cw(c324.35,120.725) 324.35,122.725 cw(c324.35,120.725) 326.35,120.725 cw(c324.35,120.725)
  pour cut-out: 324.35,127.125 cw(c324.35,129.125) 322.35,129.125 cw(c324.35,129.125) 324.35,131.125 cw(c324.35,129.125) 326.35,129.125 cw(c324.35,129.125)
  pour cut-out: 111,130 cw(c111,132) 109,132 cw(c111,132) 111,134 cw(c111,132) 113,132 cw(c111,132)
  pour cut-out: 64,130 cw(c64,132) 62,132 cw(c64,132) 64,134 cw(c64,132) 66,132 cw(c64,132)
  pour cut-out: 41,130 cw(c41,132) 39,132 cw(c41,132) 41,134 cw(c41,132) 43,132 cw(c41,132)
  pour cut-out: 134.9,78.4 cw(c134.9,80.4) 132.9,80.4 cw(c134.9,80.4) 134.9,82.4 cw(c134.9,80.4) 136.9,80.4 cw(c134.9,80.4)
  pour cut-out: 231.8,73 cw(c231.8,75) 229.8,75 cw(c231.8,75) 231.8,77 cw(c231.8,75) 233.8,75 cw(c231.8,75)
Inner Layer 2:
  pour cut-out: 79.354,30.625 79.354,26.375 79.025,26.375 79.025,30.625
  pour cut-out: 89.546,30.625 89.546,26.375 89.975,26.375 89.975,30.625
  pour cut-out: 92.454,30.625 92.454,26.375 92.025,26.375 92.025,30.625
  pour cut-out: 98.646,30.625 98.646,26.375 98.975,26.375 98.975,30.625
  pour cut-out: 108,49 cw(c108,51) 106,51 cw(c108,51) 108,53 cw(c108,51) 110,51 cw(c108,51)
  pour cut-out: 78,79 cw(c78,81) 76,81 cw(c78,81) 78,83 cw(c78,81) 80,81 cw(c78,81)
  pour cut-out: 41,41 cw(c41,43) 39,43 cw(c41,43) 41,45 cw(c41,43) 43,43 cw(c41,43)
  pour cut-out: 41,130 cw(c41,132) 39,132 cw(c41,132) 41,134 cw(c41,132) 43,132 cw(c41,132)
  pour cut-out: 64,130 cw(c64,132) 62,132 cw(c64,132) 64,134 cw(c64,132) 66,132 cw(c64,132)
  pour cut-out: 111,130 cw(c111,132) 109,132 cw(c111,132) 111,134 cw(c111,132) 113,132 cw(c111,132)
  pour cut-out: 326.2,53.9 cw(c326.2,55.9) 324.2,55.9 cw(c326.2,55.9) 326.2,57.9 cw(c326.2,55.9) 328.2,55.9 cw(c326.2,55.9)
  pour cut-out: 326.2,111.5 cw(c326.2,113.5) 324.2,113.5 cw(c326.2,113.5) 326.2,115.5 cw(c326.2,113.5) 328.2,113.5 cw(c326.2,113.5)
  pour cut-out: 324.35,118.725 cw(c324.35,120.725) 322.35,120.725 cw(c324.35,120.725) 324.35,122.725 cw(c324.35,120.725) 326.35,120.725 cw(c324.35,120.725)
  pour cut-out: 324.35,127.125 cw(c324.35,129.125) 322.35,129.125 cw(c324.35,129.125) 324.35,131.125 cw(c324.35,129.125) 326.35,129.125 cw(c324.35,129.125)
  pour cut-out: 121,130 cw(c121,132) 119,132 cw(c121,132) 121,134 cw(c121,132) 123,132 cw(c121,132)
  pour cut-out: 168,130 cw(c168,132) 166,132 cw(c168,132) 168,134 cw(c168,132) 170,132 cw(c168,132)
  pour cut-out: 178,130 cw(c178,132) 176,132 cw(c178,132) 178,134 cw(c178,132) 180,132 cw(c178,132)
  pour cut-out: 225,130 cw(c225,132) 223,132 cw(c225,132) 225,134 cw(c225,132) 227,132 cw(c225,132)
  pour cut-out: 235,130 cw(c235,132) 233,132 cw(c235,132) 235,134 cw(c235,132) 237,132 cw(c235,132)
  pour cut-out: 282,130 cw(c282,132) 280,132 cw(c282,132) 282,134 cw(c282,132) 284,132 cw(c282,132)
  pour cut-out: 134.9,78.4 cw(c134.9,80.4) 132.9,80.4 cw(c134.9,80.4) 134.9,82.4 cw(c134.9,80.4) 136.9,80.4 cw(c134.9,80.4)
  pour cut-out: 231.8,73 cw(c231.8,75) 229.8,75 cw(c231.8,75) 231.8,77 cw(c231.8,75) 233.8,75 cw(c231.8,75)
GND Layer 1:
  pour cut-out: 41,130 cw(c41,132) 39,132 cw(c41,132) 41,134 cw(c41,132) 43,132 cw(c41,132)
  pour cut-out: 64,130 cw(c64,132) 62,132 cw(c64,132) 64,134 cw(c64,132) 66,132 cw(c64,132)
  pour cut-out: 111,130 cw(c111,132) 109,132 cw(c111,132) 111,134 cw(c111,132) 113,132 cw(c111,132)
  pour cut-out: 121,130 cw(c121,132) 119,132 cw(c121,132) 121,134 cw(c121,132) 123,132 cw(c121,132)
  pour cut-out: 168,130 cw(c168,132) 166,132 cw(c168,132) 168,134 cw(c168,132) 170,132 cw(c168,132)
  pour cut-out: 178,130 cw(c178,132) 176,132 cw(c178,132) 178,134 cw(c178,132) 180,132 cw(c178,132)
  pour cut-out: 225,130 cw(c225,132) 223,132 cw(c225,132) 225,134 cw(c225,132) 227,132 cw(c225,132)
  pour cut-out: 235,130 cw(c235,132) 233,132 cw(c235,132) 235,134 cw(c235,132) 237,132 cw(c235,132)
  pour cut-out: 282,130 cw(c282,132) 280,132 cw(c282,132) 282,134 cw(c282,132) 284,132 cw(c282,132)
  pour cut-out: 324.35,127.125 cw(c324.35,129.125) 322.35,129.125 cw(c324.35,129.125) 324.35,131.125 cw(c324.35,129.125) 326.35,129.125 cw(c324.35,129.125)
  pour cut-out: 324.35,118.725 cw(c324.35,120.725) 322.35,120.725 cw(c324.35,120.725) 324.35,122.725 cw(c324.35,120.725) 326.35,120.725 cw(c324.35,120.725)
  pour cut-out: 326.2,111.5 cw(c326.2,113.5) 324.2,113.5 cw(c326.2,113.5) 326.2,115.5 cw(c326.2,113.5) 328.2,113.5 cw(c326.2,113.5)
  pour cut-out: 326.2,53.9 cw(c326.2,55.9) 324.2,55.9 cw(c326.2,55.9) 326.2,57.9 cw(c326.2,55.9) 328.2,55.9 cw(c326.2,55.9)
  pour cut-out: 108,49 cw(c108,51) 106,51 cw(c108,51) 108,53 cw(c108,51) 110,51 cw(c108,51)
  pour cut-out: 78,79 cw(c78,81) 76,81 cw(c78,81) 78,83 cw(c78,81) 80,81 cw(c78,81)
  pour cut-out: 41,41 cw(c41,43) 39,43 cw(c41,43) 41,45 cw(c41,43) 43,43 cw(c41,43)
  pour cut-out: 134.9,78.4 cw(c134.9,80.4) 132.9,80.4 cw(c134.9,80.4) 134.9,82.4 cw(c134.9,80.4) 136.9,80.4 cw(c134.9,80.4)
  pour cut-out: 231.8,73 cw(c231.8,75) 229.8,75 cw(c231.8,75) 231.8,77 cw(c231.8,75) 233.8,75 cw(c231.8,75)
GND Layer 2:
  pour cut-out: 41,130 cw(c41,132) 39,132 cw(c41,132) 41,134 cw(c41,132) 43,132 cw(c41,132)
  pour cut-out: 64,130 cw(c64,132) 62,132 cw(c64,132) 64,134 cw(c64,132) 66,132 cw(c64,132)
  pour cut-out: 111,130 cw(c111,132) 109,132 cw(c111,132) 111,134 cw(c111,132) 113,132 cw(c111,132)
  pour cut-out: 121,130 cw(c121,132) 119,132 cw(c121,132) 121,134 cw(c121,132) 123,132 cw(c121,132)
  pour cut-out: 168,130 cw(c168,132) 166,132 cw(c168,132) 168,134 cw(c168,132) 170,132 cw(c168,132)
  pour cut-out: 178,130 cw(c178,132) 176,132 cw(c178,132) 178,134 cw(c178,132) 180,132 cw(c178,132)
  pour cut-out: 225,130 cw(c225,132) 223,132 cw(c225,132) 225,134 cw(c225,132) 227,132 cw(c225,132)
  pour cut-out: 235,130 cw(c235,132) 233,132 cw(c235,132) 235,134 cw(c235,132) 237,132 cw(c235,132)
  pour cut-out: 282,130 cw(c282,132) 280,132 cw(c282,132) 282,134 cw(c282,132) 284,132 cw(c282,132)
  pour cut-out: 324.35,127.125 cw(c324.35,129.125) 322.35,129.125 cw(c324.35,129.125) 324.35,131.125 cw(c324.35,129.125) 326.35,129.125 cw(c324.35,129.125)
  pour cut-out: 324.35,118.725 cw(c324.35,120.725) 322.35,120.725 cw(c324.35,120.725) 324.35,122.725 cw(c324.35,120.725) 326.35,120.725 cw(c324.35,120.725)
  pour cut-out: 326.2,111.5 cw(c326.2,113.5) 324.2,113.5 cw(c326.2,113.5) 326.2,115.5 cw(c326.2,113.5) 328.2,113.5 cw(c326.2,113.5)
  pour cut-out: 326.2,53.9 cw(c326.2,55.9) 324.2,55.9 cw(c326.2,55.9) 326.2,57.9 cw(c326.2,55.9) 328.2,55.9 cw(c326.2,55.9)
  pour cut-out: 108,49 cw(c108,51) 106,51 cw(c108,51) 108,53 cw(c108,51) 110,51 cw(c108,51)
  pour cut-out: 78,79 cw(c78,81) 76,81 cw(c78,81) 78,83 cw(c78,81) 80,81 cw(c78,81)
  pour cut-out: 41,41 cw(c41,43) 39,43 cw(c41,43) 41,45 cw(c41,43) 43,43 cw(c41,43)
  pour cut-out: 134.9,78.4 cw(c134.9,80.4) 132.9,80.4 cw(c134.9,80.4) 134.9,82.4 cw(c134.9,80.4) 136.9,80.4 cw(c134.9,80.4)
  pour cut-out: 231.8,73 cw(c231.8,75) 229.8,75 cw(c231.8,75) 231.8,77 cw(c231.8,75) 233.8,75 cw(c231.8,75)
Solder Side:
  pour cut-out: 319.3,108.2 319.3,106.4 323.4,106.4 323.4,108.2
  pour cut-out: 319.25,51.5 319.25,49.7 323.35,49.7 323.35,51.5
  pour cut-out: 65.9,64.55 65.9,63.6 64.7,63.6 64.7,64.55
  pour cut-out: 303.35,91.9 303.35,96 303.05,96 303.05,91.9
  pour cut-out: 301.95,91.9 301.95,96 301.65,96 301.65,91.9
  pour cut-out: 303.35,83.8 303.35,87.9 303.05,87.9 303.05,83.8
  pour cut-out: 301.95,83.8 301.95,87.9 301.65,87.9 301.65,83.8
  pour cut-out: 282,130 cw(c282,132) 280,132 cw(c282,132) 282,134 cw(c282,132) 284,132 cw(c282,132)
  pour cut-out: 235,130 cw(c235,132) 233,132 cw(c235,132) 235,134 cw(c235,132) 237,132 cw(c235,132)
  pour cut-out: 225,130 cw(c225,132) 223,132 cw(c225,132) 225,134 cw(c225,132) 227,132 cw(c225,132)
  pour cut-out: 178,130 cw(c178,132) 176,132 cw(c178,132) 178,134 cw(c178,132) 180,132 cw(c178,132)
  pour cut-out: 168,130 cw(c168,132) 166,132 cw(c168,132) 168,134 cw(c168,132) 170,132 cw(c168,132)
  pour cut-out: 121,130 cw(c121,132) 119,132 cw(c121,132) 121,134 cw(c121,132) 123,132 cw(c121,132)
  pour cut-out: 328.2,132.5 cw(c328.2,134) 326.7,134 cw(c328.2,134) 328.2,135.5 cw(c328.2,134) 329.7,134 cw(c328.2,134)
  region: 328.2,133.5 cw(c328.2,134) 327.7,134 cw(c328.2,134) 328.2,134.5 cw(c328.2,134) 328.7,134 cw(c328.2,134)
  pour cut-out: 328.2,38.5 cw(c328.2,40) 326.7,40 cw(c328.2,40) 328.2,41.5 cw(c328.2,40) 329.7,40 cw(c328.2,40)
  region: 328.2,39.5 cw(c328.2,40) 327.7,40 cw(c328.2,40) 328.2,40.5 cw(c328.2,40) 328.7,40 cw(c328.2,40)
  pour cut-out: 36,133 cw(c36,134.5) 34.5,134.5 cw(c36,134.5) 36,136 cw(c36,134.5) 37.5,134.5 cw(c36,134.5)
  region: 36,134 cw(c36,134.5) 35.5,134.5 cw(c36,134.5) 36,135 cw(c36,134.5) 36.5,134.5 cw(c36,134.5)
  pour cut-out: 326.2,53.9 cw(c326.2,55.9) 324.2,55.9 cw(c326.2,55.9) 326.2,57.9 cw(c326.2,55.9) 328.2,55.9 cw(c326.2,55.9)
  pour cut-out: 326.2,111.5 cw(c326.2,113.5) 324.2,113.5 cw(c326.2,113.5) 326.2,115.5 cw(c326.2,113.5) 328.2,113.5 cw(c326.2,113.5)
  pour cut-out: 324.35,118.725 cw(c324.35,120.725) 322.35,120.725 cw(c324.35,120.725) 324.35,122.725 cw(c324.35,120.725) 326.35,120.725 cw(c324.35,120.725)
  pour cut-out: 324.35,127.125 cw(c324.35,129.125) 322.35,129.125 cw(c324.35,129.125) 324.35,131.125 cw(c324.35,129.125) 326.35,129.125 cw(c324.35,129.125)
  pour cut-out: 111,130 cw(c111,132) 109,132 cw(c111,132) 111,134 cw(c111,132) 113,132 cw(c111,132)
  pour cut-out: 64,130 cw(c64,132) 62,132 cw(c64,132) 64,134 cw(c64,132) 66,132 cw(c64,132)
  pour cut-out: 41,130 cw(c41,132) 39,132 cw(c41,132) 41,134 cw(c41,132) 43,132 cw(c41,132)
  pour cut-out: 41,41 cw(c41,43) 39,43 cw(c41,43) 41,45 cw(c41,43) 43,43 cw(c41,43)
  pour cut-out: 108,49 cw(c108,51) 106,51 cw(c108,51) 108,53 cw(c108,51) 110,51 cw(c108,51)
  pour cut-out: 78,79 cw(c78,81) 76,81 cw(c78,81) 78,83 cw(c78,81) 80,81 cw(c78,81)
  pour cut-out: 134.9,78.4 cw(c134.9,80.4) 132.9,80.4 cw(c134.9,80.4) 134.9,82.4 cw(c134.9,80.4) 136.9,80.4 cw(c134.9,80.4)
  pour cut-out: 231.8,73 cw(c231.8,75) 229.8,75 cw(c231.8,75) 231.8,77 cw(c231.8,75) 233.8,75 cw(c231.8,75)

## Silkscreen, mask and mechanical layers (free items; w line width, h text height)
Top Overlay:
  drawing of 238 lines, arcs and shapes, not listed
  text "1b" at 293.4,133.4 h1.01
  text "1" at 300.9,133.4 h1.01
  text "1a" at 307.7,133.3 h1.01
  text "ON" at 289,132 h1.01
  text "OFF" at 311.7,132 h1.01
  text "TX LED" at 37.7,127.6 h1.01
  text "RX LED" at 49.2,124.2 h1.01
  text "1986BE92" at 71.2,117.7 h1.01
  text "8MHz" at 79.1,103.5 h1.01
  text "GND" at 322.5,93.8 h1.01
  text "1923KX028" at 92.3,79.9 h1.01
  text "MODE 1923KX028" at 59.4,78.6 h1.01
  text "M0" at 61.3,76.3 h1.01
  text "M1" at 64,76.3 h1.01
  text "M2" at 66.3,76.3 h1.01
  text "M3" at 68.8,76.3 h1.01
  text "GND" at 322.5,74.3 h1.01
  text "0" at 71.4,70.4 h1.01
  text "PROG / PWR" at 38.5,68.7 h1.01
  text "BRD / PWR" at 45.3,68.7 h1.01
  text "TEST" at 76.2,66.5 h1.01 r90
  text "1" at 71.7,66 h1.01
  text "+12V" at 305.1,64.4 h1.01 r90
  text "+1.1V" at 295.9,64.1 h1.01 r90
  text "+3.3V" at 291.4,64 h1.01 r90
  text "CLK_3VP" at 117.3,60.7 h1.01
  text "nTRST" at 56.6,58.6 h1.01
  text "MRST" at 45,57.5 h1.01 r90
  text "SEL_SPI" at 51.9,56 h1.01 r90
  text "PLLOUT" at 113.4,54.3 h1.01
  text "25MHz" at 118,46.9 h1.01
  text "SPEED_MODE[0]" at 47.6,43.5 h1.01
  text "RDLH" at 67.3,43.5 h1.01
  text "GND" at 168.5,43.5 h1.01
  text "SPEED_MODE[1]" at 47.6,42 h1.01
  text "SMLH" at 67.3,42 h1.01
  text "SPEED_MODE[2]" at 47.6,40.5 h1.01
  text "EVALUATION BOARD / FOR IC 1923KX028 / MILANDR, 2018 / REV. 1.0" at 151,40 h1.01
  text "RST 1923KX028 / FROM CPU" at 82.9,37.8 h1.01
  text "PCI-E x1" at 82.8,34.1 h1.01
Bottom Overlay:
  drawing of 192 lines, arcs and shapes, not listed
  text "MODE[2]" at 75.5,122.1 h1.01
  text "MODE[1]" at 75.5,120.7 h1.01
  text "MODE[0]" at 75.5,119.3 h1.01
  text "1" at 49.6,111.3 h1.01
  text "0" at 55.2,111.3 h1.01
  text "MCU" at 57.3,107.4 h1.01
  text "RESET" at 57.3,105.9 h1.01
  text "MCU JTAG" at 36,101.8 h1.01 r90
  text "1923KX028 / RESET" at 65.6,95.8 h1.01
  text "GND" at 325.4,94 h1.01
  text "NOT CONN" at 73.7,82.5 h1.01
  text "SPI CONNECTION" at 52.3,77.9 h1.01
  text "1" at 123.7,77.4 h1.01
  text "0" at 131.8,77.4 h1.01
  text "SA5-FLASH to 1923" at 52.3,76.1 h1.01
  text "F3" at 135.3,75.2 h1.01
  text "GND" at 325.4,74.5 h1.01
  text "SA6-MCU to 1923" at 52.3,74.3 h1.01
  text "F2" at 135.4,72.7 h1.01
  text "F1" at 135.4,70.2 h1.01
  text "CONNECTED" at 73.8,69.5 h1.01
  text "F0" at 135.4,67.6 h1.01
  text "1923KX028 SPI / MASTER CLOCK /       SELECT" at 133.8,61.4 h1.01
  text "SA4" at 140.4,54.5 h1.01
  text "SA4" at 151.3,54.5 h1.01
  text "GENERAL / CLCOK / SELECT / (25 MHz / FOR 1923)" at 133.5,45.2 h1.01
  text "GND" at 171.4,43.7 h1.01
  text "OSCILLATOR / CONFIG" at 155,40.1 h1.01
  text "QUARTZ / CRYSTAL / CONFIG" at 142,38.5 h1.01
Top Solder:
  region: 67.2,34 67.2,29.4 75.2,29.4 75.2,34
  region: 171.5,38 171.5,43 168.5,43 168.5,38
  region: 328.2,132.5 cw(c328.2,134) 326.7,134 cw(c328.2,134) 328.2,135.5 cw(c328.2,134) 329.7,134 cw(c328.2,134)
  region: 79,50.5 cw(c79,52) 77.5,52 cw(c79,52) 79,53.5 cw(c79,52) 80.5,52 cw(c79,52)
  region: 36,133 cw(c36,134.5) 34.5,134.5 cw(c36,134.5) 36,136 cw(c36,134.5) 37.5,134.5 cw(c36,134.5)
  region: 328.2,38.5 cw(c328.2,40) 326.7,40 cw(c328.2,40) 328.2,41.5 cw(c328.2,40) 329.7,40 cw(c328.2,40)
Bottom Solder:
  region: 67.2,34 75.2,34 75.2,29.4 67.2,29.4
  region: 171.5,38 171.5,43 168.5,43 168.5,38
  region: 328.2,38.5 cw(c328.2,40) 326.7,40 cw(c328.2,40) 328.2,41.5 cw(c328.2,40) 329.7,40 cw(c328.2,40)
  region: 328.2,132.5 cw(c328.2,134) 326.7,134 cw(c328.2,134) 328.2,135.5 cw(c328.2,134) 329.7,134 cw(c328.2,134)
  region: 84.75,55 ccw(c85,55) 85,54.75 ccw(c85,55) 85.25,55 ccw(c85,55) 85,55.25 ccw(c85,55)
  region: 84.75,54 ccw(c85,54) 85,53.75 ccw(c85,54) 85.25,54 ccw(c85,54) 85,54.25 ccw(c85,54)
  region: 94.35,41.6 ccw(c94.6,41.6) 94.6,41.35 ccw(c94.6,41.6) 94.85,41.6 ccw(c94.6,41.6) 94.6,41.85 ccw(c94.6,41.6)
  region: 95.15,41.6 ccw(c95.4,41.6) 95.4,41.35 ccw(c95.4,41.6) 95.65,41.6 ccw(c95.4,41.6) 95.4,41.85 ccw(c95.4,41.6)
  region: 90.75,57 ccw(c91,57) 91,56.75 ccw(c91,57) 91.25,57 ccw(c91,57) 91,57.25 ccw(c91,57)
  region: 90.75,58 ccw(c91,58) 91,57.75 ccw(c91,58) 91.25,58 ccw(c91,58) 91,58.25 ccw(c91,58)
  region: 102.75,66 ccw(c103,66) 103,65.75 ccw(c103,66) 103.25,66 ccw(c103,66) 103,66.25 ccw(c103,66)
  region: 101.75,66 ccw(c102,66) 102,65.75 ccw(c102,66) 102.25,66 ccw(c102,66) 102,66.25 ccw(c102,66)
  region: 36,133 cw(c36,134.5) 34.5,134.5 cw(c36,134.5) 36,136 cw(c36,134.5) 37.5,134.5 cw(c36,134.5)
